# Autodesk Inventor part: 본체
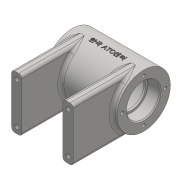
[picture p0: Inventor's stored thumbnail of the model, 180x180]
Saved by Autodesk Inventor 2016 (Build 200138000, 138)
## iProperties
Created: 2020-07
Part Number: 본체
Material: Generic
Document SubType Name: Modeling
Designer: USER
Density: 1 g/cm^3
Appearance: Default
Mass: 113.055 g
Surface Area: 357.573 cm^2
Volume: 113.055 cm^3
Author: USER
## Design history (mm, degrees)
sketch "스케치1"
  geometry: L1 (-35, 0)-(35, 0); L2 (-35, 0)-(-35, 26); L3 (-35, 26)-(35, 26); L4 (35, 26)-(35, 0); L5 (-35, 16)-(-23, 16); L6 (-23, 16)-(-23, 14); L7 (-23, 14)-(-21, 14); L8 (-21, 14)-(-21, 21); L9 (-21, 21)-(21, 21); L10 (21, 21)-(21, 14); L11 (21, 14)-(23, 14); L12 (23, 14)-(23, 16); L13 (23, 16)-(35, 16); 2 further points
  constraints: 26 end point, 10 perpendicular, 2 horizontal, 2 point on line, 1 coincident, 1 midpoint, 1 vertical
  dimensions: "d0" = 32 diameter of L5 L1; "d1" = 28 diameter of L7 L1; "d2" = 42 diameter of L9 L1; "d3" = 28 diameter of L11 L1; "d4" = 32 diameter of L13 L1; "d5" = 52 diameter of L3 L1; "d6" = 12 distance of L5.start L5.end; "d7" = 2 distance of L6.end L7.end; "d8" = 12 distance of L12.end L13.end; "d9" = 42 distance of L8.end L9.end; "d10" = 2 distance of L10.end L11.end
revolve "회전1" sketch "스케치1" stored, may be unused: angle "d11" = 90 deg
node "작업 평면1"
sketch "스케치2"
  geometry: L1 (0, -26)-(-64, -26); L2 (-64, -26)-(-64, 26); L3 (-64, 26)-(0, 26); A1 r 26 centre (0, 0) between (0, -26) and (0, 26) reference; 2 further points
  constraints: 6 end point, 2 perpendicular, 2 point on circle, 1 horizontal, 1 horizontal alignment, 1 midpoint
  dimensions: "d13" = 52 distance of L1.end L2.end; "d60" = 64 distance from line of L2 point (0, 0)
extrude "돌출1" join sketch "스케치2" distance "d14" = 10; taper "d15" = 0 deg
node "작업 평면2"
sketch "스케치3"
  geometry: C1 r 5 at (0, 0); 1 further point
  constraints: 1 centre point, 1 coincident
  dimensions: "d17" = 10 diameter of C1
extrude "돌출2" join sketch "스케치3" stored distance "d18" = 10; taper "d19" = 0 deg
sketch "스케치4"
  geometry: 1 further point
hole "구멍1" sketch "스케치4" at (0, 0) diameter "d20" = 5.188; stored, may be unused: countersink angle "d24" = 90 deg, drill point angle "d26" = 118 deg; dims "d21" = 12, "d22" = 4, "d23" = 2, "d25" = 16
sketch "스케치5"
  geometry: L1 (29, -5)-(25.515, -5) reference; L2 (25.515, 5)-(29, 5) reference; L3 (29, 5)-(29, 2.594) reference; L4 (29, 2.594)-(20.839, 2.594) reference; L5 (20.839, -2.594)-(29, -2.594) reference; L6 (29, -2.594)-(29, -5) reference; L7 (0, 0)-(-27.251, -9.919); L8 (0, 0)-(-26, 0); L9 (-27.251, -9.919)-(-29.303, -4.28); L10 (-29.303, -4.28)-(-25.825, -3.014); A1 r 26 centre (0, 0) between (25.515, 5) and (25.515, -5) reference; A2 r 21 centre (0, 0) between (20.839, 2.594) and (20.839, -2.594) reference; A3 r 26 centre (0, 0) between (0, 26) and (0, -26) reference; A4 r 26 centre (0, 0) between (-26, 0) and (-24.432, -8.893); 1 further point
  constraints: 10 end point, 3 point on circle, 2 perpendicular, 1 centre point, 1 coincident, 1 horizontal, 1 point on line
  dimensions: "d27" = 20 deg angle of L8 L7; "d28" = 29 distance of L7.end point (0, 0); "d30" = 12 diameter of L10 L7
revolve "회전2" sketch "스케치5" stored, may be unused: angle "d29" = 90 deg
sketch "스케치6"
  geometry: 1 further point
hole "구멍2" sketch "스케치6" at (0, 0) diameter "d31" = 5.188; stored, may be unused: countersink angle "d35" = 90 deg, drill point angle "d37" = 118 deg; dims "d32" = 12, "d33" = 4, "d34" = 2, "d36" = 16
sketch "스케치7"
  geometry: L1 (-50, 0)-(-60, 0) reference; L2 (-60, 0)-(-60, 52) reference; L3 (-60, 52)-(-50, 52) reference; L4 (-50, 52)-(-50, 0) reference; L5 (0, 0)-(-10, 0) reference; L6 (-10, 0)-(-10, 52) reference; L7 (-10, 52)-(0, 52) reference; L8 (0, 52)-(0, 0) reference; L9 (-5, 6)-(-5, 46); 2 further points
  constraints: 2 end point, 1 horizontal alignment, 1 midpoint, 1 vertical
  dimensions: "d38" = 40 distance of L9.start L9.end; "d39" = 5 distance between parallel lines of L8 L9
hole "구멍3" sketch "스케치7" at (-5, 6), (-5, 46) diameter "d40" = 4.134; stored, may be unused: countersink angle "d44" = 90 deg, drill point angle "d46" = 118 deg; dims "d41" = 8, "d42" = 4, "d43" = 2, "d45" = 10
sketch "스케치8"
  geometry: L1 (0, 0)-(0, 21)
  constraints: 2 end point, 1 vertical
  dimensions: "d47" = 21 distance of L1.start L1.end
hole "구멍4" sketch "스케치8" at (0, 21) diameter "d48" = 3.242; stored, may be unused: countersink angle "d52" = 90 deg, drill point angle "d54" = 118 deg; dims "d49" = 8, "d50" = 4, "d51" = 2, "d53" = 10
sketch "스케치9"
  geometry: L1 (-5, 38)-(-5, 90) reference; L2 (60, 0)-(50, 0) reference; L3 (50, 0)-(50, 64) reference; L4 (50, 64)-(60, 64) reference; L5 (60, 64)-(65, 64) reference; L6 (60, 64)-(60, 0) reference; L7 (10, 64)-(50, 64) reference; L8 (0, 64)-(10, 64) reference; L9 (-5, 64)-(0, 64) reference; L10 (10, 64)-(10, 0) reference; L11 (10, 0)-(0, 0) reference; L12 (0, 0)-(0, 64) reference; 2 further points
  constraints: 1 other
  dimensions: "d69" = 35 distance from line of L1 point (30, 64); "d70" = 26 vertical distance of L1.end point (30, 64)
feature "엠보싱1" sketch "스케치9" dims "d0" = 32, "d1" = 28, "d2" = 42, "d3" = 28, "d4" = 32, "d5" = 52, "d6" = 12, "d7" = 2, "d8" = 12, "d9" = 42, "d10" = 2, "d13" = 52, "d58" = 0.5, "d59" = 0, "d60" = 64
fillet "모깎기1" dims "d61" = 3
fillet "모깎기2" dims "d62" = 3
fillet "모깎기3" dims "d63" = 2
fillet "모깎기4" dims "d64" = 0.3
fillet "모깎기5" dims "d65" = 3
chamfer "모따기1" distance "d66" = 1; stored, may be unused: second distance "d67" = 2, angle "d68" = 45 deg
node "솔리드1"
mirror "대칭1"
mirror "대칭2"
pattern_circular "원형 패턴1" dims angle "d56" = 360 deg
mirror "대칭3"
node "절단 모서리 투영1"
node "절단 모서리 투영2"
node "절단 모서리 투영3"
other parameters: "d16" = 29
